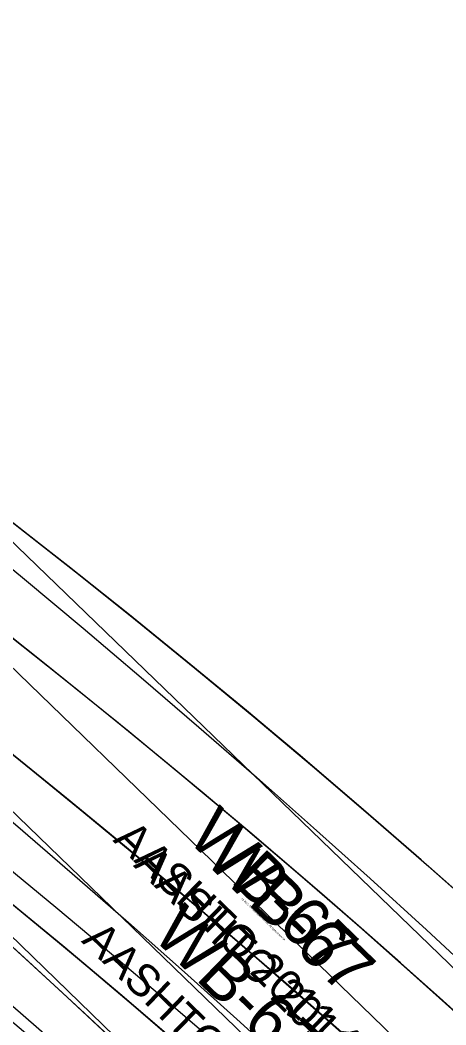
# Model space of a CAD drawing. Extents: x 916040 to 917457, y 328936 to 330267.
# Drawn here: x 916532.53 to 916551.21, y 329994 to 330038.14 of the extents above; entities that cross this region are included whole.
import ezdxf

# ---------------------------------------------------------------- set-up
doc = ezdxf.new("R2010")
doc.units = 0
for name, color, linetype in [('EB_LeftontoManchester_WB67', 7, 'Continuous'), ('EB_LeftontoManchester_WB67_v2', 7, 'Continuous'), ('NB_ThruontoManchester_WB67', 7, 'Continuous'), ('SB_LeftontoRoute25_WB67', 7, 'Continuous'), ('SB_RightontoRoute25_WB67_v2', 7, 'Continuous'), ('SB_ThruontonSacoRd_WB67', 7, 'Continuous'), ('WB_RightontoManchester_WB67', 7, 'Continuous')]:
    doc.layers.add(name, color=color, linetype=linetype)

msp = doc.modelspace()

# ---------------------------------------------------------------- linework, layer by layer
at = {"layer": 'EB_LeftontoManchester_WB67'}
for p, q in [((916565.496, 329983.001), (916527.395, 330019.843)), ((916521.487, 330013.732), (916559.587, 329976.89))]:
    msp.add_line(p, q, dxfattribs=at)
for points in [[(916552.447, 329999.205), (916549.921, 330001.436), (916547.377, 330003.645), (916544.814, 330005.832), (916542.232, 330007.997), (916539.631, 330010.14), (916537.012, 330012.261), (916534.375, 330014.358), (916531.721, 330016.434), (916529.048, 330018.486), (916526.358, 330020.515), (916523.65, 330022.521), (916520.926, 330024.504), (916518.184, 330026.463), (916515.426, 330028.398), (916513.485, 330029.739)], [(916551.793, 329989.013), (916549.355, 329991.239), (916546.898, 329993.444), (916544.423, 329995.627), (916541.929, 329997.789), (916539.416, 329999.93), (916536.885, 330002.049), (916534.336, 330004.146), (916531.769, 330006.221), (916529.184, 330008.274), (916526.581, 330010.305), (916523.962, 330012.313), (916521.325, 330014.299), (916518.671, 330016.262), (916516, 330018.202), (916513.313, 330020.119), (916510.609, 330022.013), (916508.707, 330023.325)]]:
    msp.add_lwpolyline(points, dxfattribs=at)
msp.add_arc((916291.649, 329706.552), 388, 12.26429, 55.55708, dxfattribs=at)
at = {"layer": 'EB_LeftontoManchester_WB67_v2'}
for p, q in [((916565.496, 329983.001), (916527.395, 330019.843)), ((916521.487, 330013.732), (916559.587, 329976.89))]:
    msp.add_line(p, q, dxfattribs=at)
for points in [[(916552.656, 329999.018), (916550.135, 330001.248), (916547.595, 330003.457), (916545.036, 330005.644), (916542.459, 330007.808), (916539.863, 330009.951), (916537.249, 330012.071), (916534.617, 330014.168), (916531.966, 330016.243), (916529.298, 330018.295), (916526.613, 330020.324), (916523.91, 330022.33), (916521.19, 330024.313), (916518.453, 330026.272), (916515.7, 330028.207), (916513.485, 330029.739)], [(916551.989, 329988.832), (916549.556, 329991.057), (916547.103, 329993.261), (916544.632, 329995.444), (916542.142, 329997.605), (916539.634, 329999.746), (916537.108, 330001.864), (916534.563, 330003.961), (916532, 330006.035), (916529.42, 330008.088), (916526.822, 330010.119), (916524.207, 330012.127), (916521.575, 330014.112), (916518.925, 330016.075), (916516.259, 330018.015), (916513.577, 330019.932), (916510.878, 330021.826), (916508.707, 330023.325)]]:
    msp.add_lwpolyline(points, dxfattribs=at)
msp.add_arc((916291.649, 329706.552), 388, 12.26429, 55.55708, dxfattribs=at)
at = {"layer": 'NB_ThruontoManchester_WB67'}
for points in [[(916500.979, 330038.139), (916503.681, 330036.168), (916506.374, 330034.185), (916509.059, 330032.189), (916511.733, 330030.18), (916514.398, 330028.158), (916517.052, 330026.121), (916519.695, 330024.07), (916522.326, 330022.003), (916524.945, 330019.921), (916527.551, 330017.823), (916530.144, 330015.708), (916532.723, 330013.577), (916535.289, 330011.429), (916537.839, 330009.264), (916540.375, 330007.082), (916542.896, 330004.882), (916545.401, 330002.664), (916547.89, 330000.428), (916550.363, 329998.175), (916552.819, 329995.903)], [(916513.358, 330029.831), (916516.109, 330027.927), (916518.847, 330025.997), (916521.57, 330024.042), (916524.279, 330022.062), (916526.973, 330020.058), (916529.651, 330018.029), (916532.313, 330015.977), (916534.958, 330013.901), (916537.586, 330011.801), (916540.197, 330009.679), (916542.79, 330007.534), (916545.365, 330005.366), (916547.922, 330003.176), (916550.461, 330000.963), (916552.98, 329998.729)], [(916501.321, 330027.35), (916503.973, 330025.378), (916506.614, 330023.395), (916509.243, 330021.399), (916511.861, 330019.391), (916514.466, 330017.369), (916517.058, 330015.333), (916519.637, 330013.282), (916522.202, 330011.217), (916524.753, 330009.136), (916527.29, 330007.04), (916529.812, 330004.929), (916532.319, 330002.801), (916534.811, 330000.656), (916537.287, 329998.495), (916539.746, 329996.318), (916542.19, 329994.123), (916544.617, 329991.911), (916547.027, 329989.682), (916549.419, 329987.436), (916551.795, 329985.172)], [(916508.833, 330023.233), (916511.568, 330021.341), (916514.283, 330019.427), (916516.979, 330017.491), (916519.655, 330015.534), (916522.313, 330013.555), (916524.952, 330011.555), (916527.573, 330009.533), (916530.175, 330007.489), (916532.758, 330005.424), (916535.323, 330003.337), (916537.869, 330001.228), (916540.396, 329999.098), (916542.904, 329996.947), (916545.394, 329994.774), (916547.864, 329992.581), (916550.315, 329990.366), (916552.746, 329988.131)]]:
    msp.add_lwpolyline(points, dxfattribs=at)
msp.add_arc((916291.649, 329706.552), 388, 11.6689, 55.55708, dxfattribs=at)
at = {"layer": 'SB_LeftontoRoute25_WB67'}
for points in [[(916502.341, 330022.84), (916504.943, 330020.735), (916507.539, 330018.621), (916510.128, 330016.497), (916512.708, 330014.361), (916515.279, 330012.213), (916517.834, 330010.055), (916520.377, 330007.884), (916522.909, 330005.697), (916525.427, 330003.494), (916527.931, 330001.276), (916530.42, 329999.041), (916532.894, 329996.789), (916535.353, 329994.519), (916537.795, 329992.232), (916540.22, 329989.927), (916542.628, 329987.604), (916545.019, 329985.263), (916547.391, 329982.903), (916549.745, 329980.526), (916552.08, 329978.13), (916554.396, 329975.715), (916556.693, 329973.282), (916558.969, 329970.83)], [(916502.58, 330020.867), (916505.303, 330018.983), (916508.039, 330017.116), (916510.791, 330015.257), (916513.545, 330013.365), (916516.283, 330011.439), (916519.005, 330009.478), (916521.709, 330007.484), (916524.394, 330005.457), (916527.059, 330003.399), (916529.704, 330001.309), (916532.327, 329999.188), (916534.929, 329997.037), (916537.508, 329994.856), (916540.063, 329992.646), (916542.595, 329990.406), (916545.103, 329988.138), (916547.586, 329985.841), (916550.044, 329983.516), (916552.477, 329981.164), (916554.883, 329978.784), (916557.264, 329976.378), (916559.617, 329973.944), (916561.944, 329971.485)]]:
    msp.add_lwpolyline(points, dxfattribs=at)
msp.add_arc((916339.95, 329763.805), 300, 42.35327, 56.08067, dxfattribs=at)
at = {"layer": 'SB_RightontoRoute25_WB67_v2'}
for points in [[(916501.298, 330023.68), (916503.903, 330021.578), (916506.502, 330019.468), (916509.094, 330017.348), (916511.677, 330015.217), (916514.252, 330013.074), (916516.813, 330010.92), (916519.362, 330008.754), (916521.898, 330006.573), (916524.421, 330004.377), (916526.931, 330002.165), (916529.426, 329999.937), (916531.906, 329997.691), (916534.371, 329995.429), (916536.82, 329993.149), (916539.252, 329990.851), (916541.667, 329988.535), (916544.065, 329986.202), (916546.444, 329983.849), (916548.806, 329981.479), (916551.148, 329979.09), (916553.472, 329976.683)], [(916501.494, 330021.626), (916504.212, 330019.735), (916506.943, 330017.86), (916509.686, 330016.004), (916512.445, 330014.126), (916515.19, 330012.213), (916517.918, 330010.266), (916520.629, 330008.285), (916523.322, 330006.272), (916525.995, 330004.226), (916528.648, 330002.149), (916531.28, 330000.04), (916533.891, 329997.901), (916536.479, 329995.732), (916539.044, 329993.534), (916541.585, 329991.306), (916544.103, 329989.049), (916546.596, 329986.763), (916549.064, 329984.45), (916551.507, 329982.108)]]:
    msp.add_lwpolyline(points, dxfattribs=at)
msp.add_arc((916339.95, 329763.805), 300, 42.35327, 56.08067, dxfattribs=at)
at = {"layer": 'SB_ThruontonSacoRd_WB67'}
for points in [[(916552.014, 329981.616), (916549.575, 329983.964), (916547.11, 329986.284), (916544.619, 329988.578), (916542.103, 329990.843), (916539.561, 329993.081), (916536.995, 329995.29), (916534.404, 329997.471), (916531.788, 329999.623), (916529.149, 330001.745), (916526.486, 330003.839), (916523.8, 330005.902), (916521.092, 330007.936), (916518.36, 330009.939), (916515.606, 330011.911), (916512.831, 330013.853), (916510.034, 330015.764), (916507.248, 330017.651), (916504.482, 330019.549), (916501.733, 330021.46)], [(916557.762, 329970.902), (916555.423, 329973.29), (916553.058, 329975.656), (916550.667, 329977.998), (916548.252, 329980.319), (916545.815, 329982.617), (916543.356, 329984.895), (916540.879, 329987.152), (916538.384, 329989.391), (916535.874, 329991.612), (916533.35, 329993.818), (916530.814, 329996.008), (916528.268, 329998.185), (916525.714, 330000.35), (916523.152, 330002.505), (916520.584, 330004.651), (916518.012, 330006.788), (916515.437, 330008.92), (916512.86, 330011.046), (916510.282, 330013.169), (916507.705, 330015.289), (916505.129, 330017.407), (916502.554, 330019.525)]]:
    msp.add_lwpolyline(points, dxfattribs=at)
msp.add_arc((916339.95, 329763.805), 300, 42.35327, 56.08067, dxfattribs=at)
at = {"layer": 'WB_RightontoManchester_WB67'}
for p, q in [((916563.187, 329979.644), (916525.133, 330016.535)), ((916519.217, 330010.432), (916557.271, 329973.541))]:
    msp.add_line(p, q, dxfattribs=at)
for points in [[(916552.174, 329994.071), (916549.667, 329996.323), (916547.14, 329998.554), (916544.595, 330000.762), (916542.03, 330002.948), (916539.446, 330005.111), (916536.843, 330007.252), (916534.222, 330009.371), (916531.583, 330011.466), (916528.925, 330013.539), (916526.25, 330015.588), (916523.556, 330017.614), (916520.846, 330019.617), (916518.118, 330021.596), (916515.373, 330023.551), (916512.611, 330025.482), (916511.224, 330026.439)], [(916551.433, 329983.888), (916549.014, 329986.134), (916546.576, 329988.359), (916544.119, 329990.563), (916541.643, 329992.745), (916539.147, 329994.905), (916536.633, 329997.044), (916534.101, 329999.161), (916531.55, 330001.256), (916528.981, 330003.329), (916526.395, 330005.379), (916523.79, 330007.407), (916521.168, 330009.412), (916518.529, 330011.394), (916515.873, 330013.353), (916513.199, 330015.289), (916510.509, 330017.202), (916507.803, 330019.091), (916506.443, 330020.027)]]:
    msp.add_lwpolyline(points, dxfattribs=at)
msp.add_arc((916291.649, 329706.552), 384, 12.55823, 55.55708, dxfattribs=at)

# ---------------------------------------------------------------- texts
at = {"layer": 'EB_LeftontoManchester_WB67'}
for s, height, p in [('WB-67', 2.125, (916540.545, 330001.215)), ('AASHTO 2011 (US)', 1.41667, (916537.468, 330000.988))]:
    msp.add_text(s, height=height, rotation=315.9623, dxfattribs=at).set_placement(p)
at = {"layer": 'EB_LeftontoManchester_WB67_v2'}
for s, height, p in [('WB-67', 2.125, (916539.79, 330002.182)), ('AASHTO 2011 (US)', 1.41667, (916536.572, 330002.092)), ('(c) 2016 Transoft Solutions, Inc. All rights reserved.', 0.085, (916542.216, 329999.54))]:
    msp.add_text(s, height=height, rotation=315.9623, dxfattribs=at).set_placement(p)
at = {"layer": 'WB_RightontoManchester_WB67'}
for s, height, p in [('WB-67', 2.125, (916538.259, 329997.89)), ('AASHTO 2011 (US)', 1.41667, (916535.182, 329997.667))]:
    msp.add_text(s, height=height, rotation=315.8895, dxfattribs=at).set_placement(p)

doc.saveas('drawing.dxf')
